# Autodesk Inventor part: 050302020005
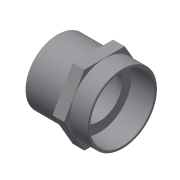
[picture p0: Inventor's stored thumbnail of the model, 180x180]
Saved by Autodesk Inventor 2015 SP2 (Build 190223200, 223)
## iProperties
Created: 2017-10
Part Number: 050302020005
Material: Generic
Description: PLASSON ADAPTOR SOCKET M.F. 20-1/2" CEM-THR
Document SubType Name: Modeling
Designer: KIM
Density: 1 g/cm^3
Appearance: Default
Author: KIM
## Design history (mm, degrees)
derived "050302.ipt"
feature "Solid1::050302.ipt"
tag "TaggingFeature1"
body "Solid1"
other parameters: "d3" = 18.631, "d4" = 14, "d6" = 12, "d8" = 23, "d13" = 0, "d14" = 0.2, "d16" = 12, "d17" = 16, "d18" = 14.4, "d20" = 16, "G_" = 18.631, "B_" = 12, "L_" = 16, "lt_" = 12
